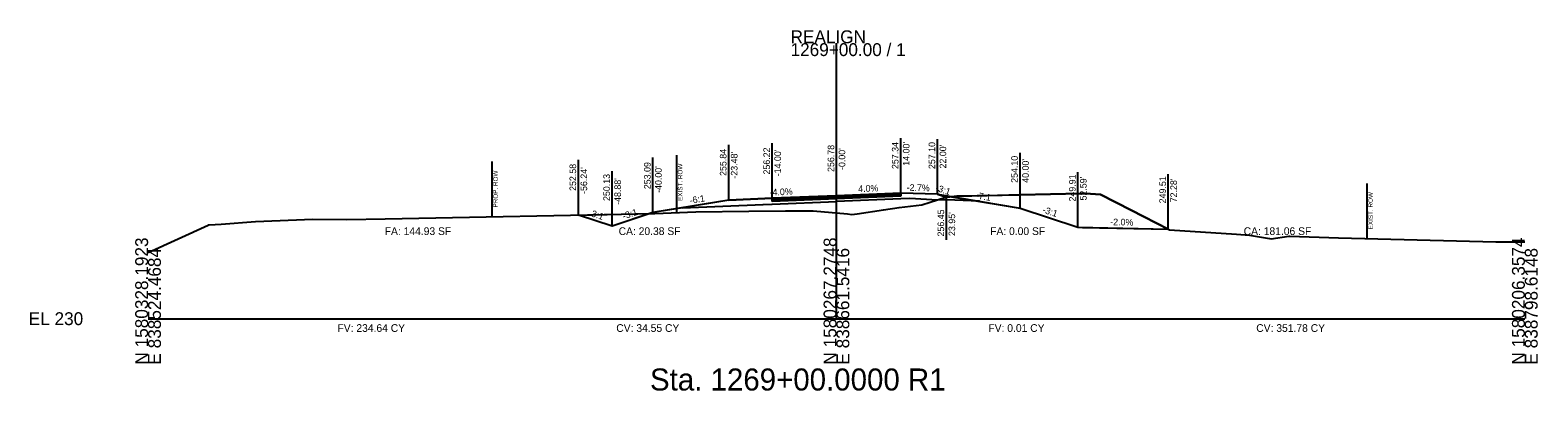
# Model space of a CAD drawing. Extents: x -26 to 6303, y -16 to 9563.
# Drawn here: x 4974.3 to 5302.8, y 1984.3 to 2062.8 of the extents above; entities that cross this region are included whole.
import ezdxf

# ---------------------------------------------------------------- set-up
doc = ezdxf.new("R2010")
doc.units = 0
for name, color, linetype in [('ASPHALT_19MM1', 7, 'Continuous'), ('ASPHALT_9_5MM1', 7, 'Continuous'), ('CONST_DCH', 7, 'Continuous'), ('CONST_LV3', 7, 'Continuous'), ('Default', 7, 'Continuous'), ('Draft_XS_Grid', 7, 'Continuous'), ('Draft_XS_Text', 7, 'Continuous'), ('DTM_TEMP_DROP', 7, 'Continuous'), ('DTM_X_GROUND', 7, 'Continuous'), ('X_TRANS_EOP', 7, 'Continuous'), ('XS_CELL', 7, 'Continuous'), ('XS_M_SHAPES_EARTHWORK', 7, 'Continuous'), ('XS_P_ASPHALT', 7, 'Continuous'), ('XS_P_GROUND', 7, 'Continuous'), ('XS_P_ROW', 7, 'Continuous'), ('XS_P_SHOULDER', 7, 'Continuous'), ('XS_P_SUBGRADE_GRANULAR', 7, 'Continuous'), ('XS_P_TX_CLEARZONE', 7, 'Continuous'), ('XS_P_TX_FS_BS', 7, 'Continuous'), ('XS_SHEET_EW_TX_AREA', 7, 'Continuous'), ('XS_SHEET_EW_TX_VOLUME', 7, 'Continuous'), ('XS_X_ROW', 7, 'Continuous')]:
    doc.layers.add(name, color=color, linetype=linetype)

msp = doc.modelspace()

# ---------------------------------------------------------------- linework, layer by layer
at = {"layer": 'ASPHALT_19MM1'}
msp.add_lwpolyline([(5136, 2025.62), (5136, 2025.62), (5136, 2025.62), (5150, 2026.18), (5150, 2026.18), (5164, 2026.74), (5164, 2026.74), (5164, 2027.01), (5150, 2026.45), (5150, 2026.45), (5136, 2025.89), (5136, 2025.89), (5136, 2025.62)], dxfattribs=at)
at = {"layer": 'ASPHALT_9_5MM1'}
msp.add_lwpolyline([(5136, 2026.1), (5136, 2026.1), (5136, 2026.1), (5150, 2026.66), (5150, 2026.66), (5164, 2027.22), (5164, 2027.22), (5164, 2027.34), (5150, 2026.78), (5150, 2026.78), (5136, 2026.22), (5136, 2026.22), (5136, 2026.1)], dxfattribs=at)
at = {"layer": 'CONST_LV3'}
for points in [[(5164, 2027.34), (5150, 2026.78), (5150, 2026.78)], [(5172, 2027.1), (5172, 2027.1), (5164, 2027.34)], [(5116.49, 2024.17), (5110, 2023.09)]]:
    msp.add_lwpolyline(points, dxfattribs=at)
at = {"layer": 'Default'}
msp.add_lwpolyline([(5136, 2025.89), (5136, 2025.89), (5136, 2025.89), (5150, 2026.45), (5150, 2026.45), (5164, 2027.01), (5164, 2027.01), (5164, 2027.22), (5150, 2026.66), (5150, 2026.66), (5136, 2026.1), (5136, 2026.1), (5136, 2025.89)], dxfattribs=at)
at = {"layer": 'DTM_X_GROUND'}
msp.add_lwpolyline([(5000, 2014.39), (5013.07, 2020.36), (5013.17, 2020.41), (5013.28, 2020.41), (5015.9, 2020.6), (5023.39, 2021.16), (5035.87, 2021.65), (5043.28, 2021.63), (5051.7, 2021.74), (5110.43, 2022.92), (5119.38, 2023.26), (5130.93, 2023.39), (5138.9, 2023.46), (5144.95, 2023.51), (5152.44, 2022.8), (5153.39, 2022.71), (5154.51, 2022.87), (5160.27, 2023.73), (5163.66, 2024.19), (5168.58, 2024.81), (5170.41, 2025.39), (5173.65, 2026.42), (5175.24, 2026.59), (5176.24, 2026.7), (5186.14, 2026.91), (5190.06, 2027), (5203.29, 2027.27), (5204.2, 2027.29), (5204.3, 2027.28), (5207.51, 2027.03), (5214.21, 2023.62), (5222.59, 2019.36), (5237.15, 2018.38), (5239.98, 2018.19), (5244.33, 2017.46), (5244.71, 2017.39), (5248.6, 2017.94), (5248.78, 2017.97), (5259.42, 2017.62), (5293.66, 2016.72), (5300, 2016.73)], dxfattribs=at)
at = {"layer": 'XS_CELL'}
for p, q in [((5150, 2000), (5150, 2060)), ((5000, 2000), (5150, 2000)), ((5150, 2000), (5300, 2000))]:
    msp.add_line(p, q, dxfattribs=at)
at = {"layer": 'XS_M_SHAPES_EARTHWORK'}
for points in [[(5109.43, 2022.9), (5110.43, 2022.92), (5119.38, 2023.26), (5130.93, 2023.39), (5138.9, 2023.46), (5144.95, 2023.51), (5152.44, 2022.8), (5153.39, 2022.71), (5154.51, 2022.87), (5160.27, 2023.73), (5163.66, 2024.19), (5168.58, 2024.81), (5170.41, 2025.39), (5173.65, 2026.42), (5173.95, 2026.45), (5172, 2027.1), (5164, 2027.34), (5164, 2027.22), (5164, 2027.01), (5164, 2026.74), (5150, 2026.18), (5136, 2025.62), (5136, 2025.89), (5136, 2026.1), (5136, 2026.22), (5126.52, 2025.84), (5116.49, 2024.17), (5110, 2023.09)], [(5093.76, 2022.58), (5109.43, 2022.9), (5101.12, 2020.13)]]:
    msp.add_lwpolyline(points, close=True, dxfattribs=at)
at = {"layer": 'XS_P_GROUND'}
for points in [[(5172, 2027.1), (5173.95, 2026.45)], [(5172, 2027.1), (5190, 2024.1), (5202.59, 2019.91)], [(5126.52, 2025.84), (5110, 2023.09), (5101.12, 2020.13)], [(5101.12, 2020.13), (5093.76, 2022.58)], [(5202.59, 2019.91), (5203.59, 2019.89)], [(5203.59, 2019.89), (5222.28, 2019.51)]]:
    msp.add_lwpolyline(points, dxfattribs=at)
at = {"layer": 'XS_P_ROW'}
msp.add_line((5075, 2022.21), (5075, 2034.21), dxfattribs=at)
at = {"layer": 'XS_P_SHOULDER'}
for points in [[(5172, 2027.1), (5172, 2027.1), (5164, 2027.34)], [(5126.52, 2025.84), (5136, 2026.22), (5136, 2026.22)]]:
    msp.add_lwpolyline(points, dxfattribs=at)
at = {"layer": 'XS_P_SUBGRADE_GRANULAR'}
for points in [[(5116.49, 2024.17), (5134, 2024.87), (5134, 2024.87), (5134, 2024.87), (5136, 2024.95)], [(5136, 2024.95), (5136, 2024.95), (5150, 2025.51)], [(5164, 2026.07), (5150, 2025.51), (5150, 2025.51)], [(5172, 2025.83), (5172, 2025.83), (5166, 2026.15), (5164, 2026.07), (5164, 2026.07)], [(5181.17, 2025.57), (5181.17, 2025.57), (5174, 2025.86), (5172, 2025.83), (5172, 2025.83)]]:
    msp.add_lwpolyline(points, dxfattribs=at)
at = {"layer": 'XS_P_TX_CLEARZONE'}
for p, q in [((5126.52, 2025.84), (5126.52, 2037.84)), ((5136, 2026.22), (5136, 2038.22)), ((5150, 2026.78), (5150, 2038.78)), ((5164, 2027.34), (5164, 2039.34)), ((5172, 2027.1), (5172, 2039.1)), ((5093.76, 2022.58), (5093.76, 2034.58)), ((5110, 2023.09), (5110, 2035.09)), ((5190, 2024.1), (5190, 2036.1)), ((5101.12, 2020.13), (5101.12, 2032.13)), ((5202.59, 2019.91), (5202.59, 2031.91)), ((5222.28, 2019.51), (5222.28, 2031.51)), ((5173.95, 2017.16), (5173.95, 2026.45))]:
    msp.add_line(p, q, dxfattribs=at)
at = {"layer": 'XS_P_TX_FS_BS'}
for p, q in [((5176.24, 2026.7), (5175.05, 2026.57)), ((5190, 2024.08), (5202.59, 2019.91)), ((5202.59, 2019.91), (5222.28, 2019.51))]:
    msp.add_line(p, q, dxfattribs=at)
for points in [[(5222.28, 2019.51), (5214.21, 2023.62), (5207.51, 2027.03), (5204.3, 2027.28), (5204.2, 2027.29), (5203.29, 2027.27), (5190.06, 2027), (5185.11, 2026.82), (5176.24, 2026.7)], [(5175.05, 2026.57), (5177.74, 2026.11), (5190, 2024.08)]]:
    msp.add_lwpolyline(points, dxfattribs=at)
at = {"layer": 'XS_X_ROW'}
for p, q in [((5115.24, 2023.1), (5115.24, 2035.64)), ((5265.68, 2017.45), (5265.68, 2029.45))]:
    msp.add_line(p, q, dxfattribs=at)

# ---------------------------------------------------------------- texts
at = {"layer": 'CONST_DCH'}
for p in [(5171.92, 2026.98), (5189.92, 2023.98)]:
    msp.add_text('X', height=0.24, dxfattribs=at).set_placement(p)
at = {"layer": 'Draft_XS_Grid'}
msp.add_text('-', height=0.0001, dxfattribs=at).set_placement((5000, 2000))
at = {"layer": 'Draft_XS_Text'}
msp.add_text('Sta. 1269+00.0000 R1', height=4.8, dxfattribs=at).set_placement((5109.37, 1984.35))
at = {"layer": 'DTM_TEMP_DROP'}
for p in [(5163.92, 2027.22), (5135.92, 2026.1), (5149.92, 2026.66)]:
    msp.add_text('X', height=0.24, dxfattribs=at).set_placement(p)
at = {"layer": 'X_TRANS_EOP'}
for p in [(5173.87, 2026.33), (5093.68, 2022.46)]:
    msp.add_text('X', height=0.24, dxfattribs=at).set_placement(p)
at = {"layer": 'XS_CELL'}
for s, p in [('1269+00.00 / 1', (5140, 2057.2)), ('REALIGN', (5140, 2060)), ('EL 230', (4974, 1998.6))]:
    msp.add_text(s, height=2.8, dxfattribs=at).set_placement(p)
for s, p in [('N 1580328.1923', (5000, 1990)), ('N 1580267.2748', (5150, 1990)), ('N 1580206.3574', (5300, 1990)), ('E 838524.4684', (5002.8, 1990)), ('E 838661.5416', (5152.8, 1990)), ('E 838798.6148', (5302.8, 1990))]:
    msp.add_text(s, height=2.8, rotation=90, dxfattribs=at).set_placement(p)
at = {"layer": 'XS_P_ASPHALT'}
msp.add_text('X', height=0.24, dxfattribs=at).set_placement((5109.92, 2022.97))
at = {"layer": 'XS_P_GROUND'}
msp.add_text('X', height=0.24, dxfattribs=at).set_placement((5171.92, 2026.98))
at = {"layer": 'XS_P_ROW'}
msp.add_text('PROP. ROW', height=1, rotation=90, dxfattribs=at).set_placement((5076.2, 2024.21))
at = {"layer": 'XS_P_SHOULDER'}
for p in [(5171.92, 2026.98), (5126.44, 2025.72), (5202.51, 2019.79)]:
    msp.add_text('X', height=0.24, dxfattribs=at).set_placement(p)
at = {"layer": 'XS_P_SUBGRADE_GRANULAR'}
for p in [(5173.87, 2026.33), (5101.05, 2020.01), (5222.21, 2019.39)]:
    msp.add_text('X', height=0.24, dxfattribs=at).set_placement(p)
at = {"layer": 'XS_P_TX_CLEARZONE'}
for s, p in [('255.84', (5126.04, 2031.09)), ('256.22', (5135.52, 2031.4)), ('256.78', (5149.52, 2031.96)), ("-0.00'", (5151.92, 2032.39)), ('257.34', (5163.52, 2032.59)), ("14.00'", (5165.92, 2033.31)), ('257.10', (5171.52, 2032.59)), ("22.00'", (5173.92, 2032.71)), ('252.58', (5093.28, 2027.83)), ('253.09', (5109.52, 2028.21)), ("-23.48'", (5128.44, 2030.5)), ("-14.00'", (5137.92, 2031.01)), ('254.10', (5189.52, 2029.59)), ("40.00'", (5191.92, 2029.6)), ("-56.24'", (5095.68, 2027.17)), ('250.13', (5100.64, 2025.63)), ("-48.88'", (5103.04, 2024.79)), ("-40.00'", (5111.92, 2027.4)), ('249.91', (5202.11, 2025.52)), ("52.59'", (5204.51, 2025.74)), ('249.51', (5221.8, 2025.12)), ("72.28'", (5224.2, 2025.35)), ('256.45', (5173.47, 2017.9)), ("23.95'", (5175.87, 2018.01))]:
    msp.add_text(s, height=1.44, rotation=90, dxfattribs=at).set_placement(p)
at = {"layer": 'XS_P_TX_FS_BS'}
for s, rotation, p in [('-4.0%', 2.2906, (5135.45, 2026.8)), ('4.0%', 2.2906, (5154.77, 2027.57)), ('-2.7%', 358.4744, (5165.28, 2027.88)), ('-3:1', 341.5651, (5171.44, 2027.92)), ('-7:1', 351.6706, (5180.27, 2026.13)), ('-3:1', 18.4332, (5103.65, 2021.6)), ('-6:1', 9.4642, (5118.15, 2025.01)), ('-3:1', 341.5651, (5194.76, 2023.15)), ('3:1', 341.5651, (5096.47, 2022.31)), ('-2.0%', 358.8542, (5209.65, 2020.37))]:
    msp.add_text(s, height=1.44, rotation=rotation, dxfattribs=at).set_placement(p)
at = {"layer": 'XS_SHEET_EW_TX_AREA'}
for s, p in [('FA: 144.93 SF', (5051.57, 2018.22)), ('CA: 20.38 SF', (5102.54, 2018.22)), ('FA: 0.00 SF', (5183.5, 2018.22)), ('CA: 181.06 SF', (5238.74, 2018.22))]:
    msp.add_text(s, height=1.68, dxfattribs=at).set_placement(p)
at = {"layer": 'XS_SHEET_EW_TX_VOLUME'}
for s, p in [('FV: 234.64 CY', (5041.27, 1997.12)), ('CV: 34.55 CY', (5102.03, 1997.12)), ('FV: 0.01 CY', (5183.11, 1997.12)), ('CV: 351.78 CY', (5241.48, 1997.12))]:
    msp.add_text(s, height=1.68, dxfattribs=at).set_placement(p)
at = {"layer": 'XS_X_ROW'}
for p in [(5116.44, 2025.64), (5266.88, 2019.45)]:
    msp.add_text('EXIST. ROW', height=1, rotation=90, dxfattribs=at).set_placement(p)

doc.saveas('drawing.dxf')
